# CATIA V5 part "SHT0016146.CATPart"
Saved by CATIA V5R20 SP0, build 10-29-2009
Part number: SHT0016146
Bounding box of the stored display mesh (mm): x -141.9 to 25.758, y -864.5 to -593.501, z 15.9 to 106.4
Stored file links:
  C:\Users\hp\Desktop\宽车主驾底支架\SHT0016146-宽车主驾驶后侧钣金\SHT0016146.CATPart
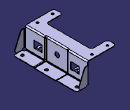
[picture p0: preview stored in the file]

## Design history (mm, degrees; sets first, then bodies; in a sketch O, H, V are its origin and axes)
Body1 (main body)
Body2 "SHT0016146-宽车主驾驶后侧钣金"
  Solid1: solid without history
